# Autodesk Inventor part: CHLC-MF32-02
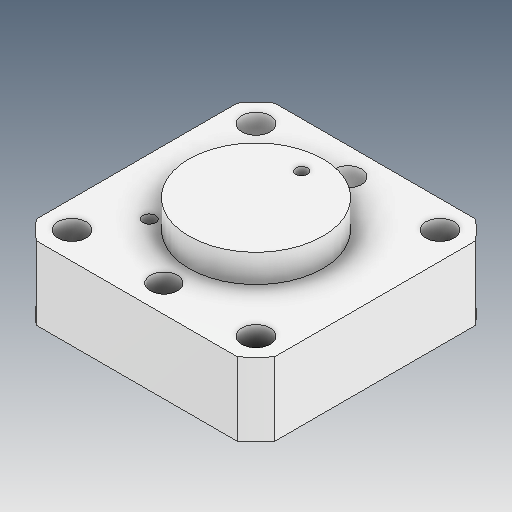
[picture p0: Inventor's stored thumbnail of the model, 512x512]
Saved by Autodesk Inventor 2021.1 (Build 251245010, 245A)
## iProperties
Created: 2021-05
Part Number: CHLC-MF32-02
Material: Ogólny
Document SubType Name: Modeling
Designer: user
Density: 1 g/cm^3
Appearance: Domyślna
Author: user
Revision Number: ÈÎºÎ
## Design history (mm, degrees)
feature "M6 ¼äÏ¶¿×1"
node "Bryła1"
